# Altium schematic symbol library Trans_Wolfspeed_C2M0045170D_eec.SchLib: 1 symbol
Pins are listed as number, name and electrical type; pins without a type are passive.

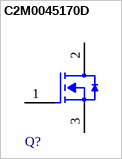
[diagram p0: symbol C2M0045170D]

## C2M0045170D
designator Q?  (value not drawn)
pins: 1 Gate, 2 Drain, 3 Source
